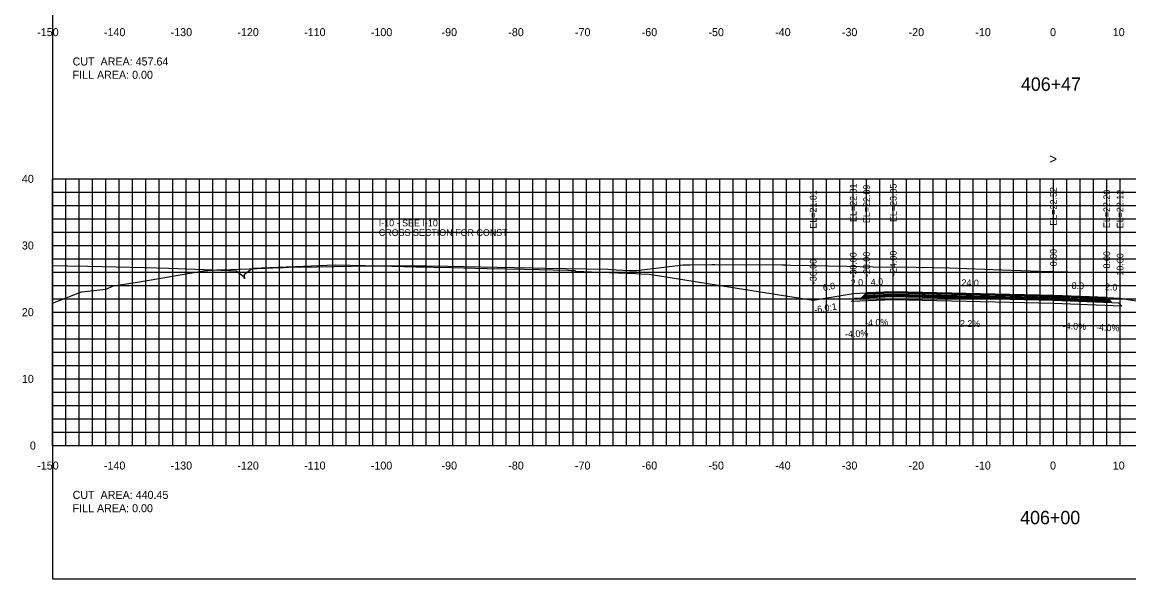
# Model space of a CAD drawing. Extents: x 1800976 to 1805104, y 250057 to 250580.
# Drawn here: x 1802816.4 to 1802982.3, y 250079.4 to 250162.9 of the extents above; entities that cross this region are included whole.
import ezdxf

# ---------------------------------------------------------------- set-up
doc = ezdxf.new("R2010")
doc.units = 0
for name, color, linetype in [('1', 7, 'Continuous'), ('10', 7, 'Continuous'), ('3', 7, 'Continuous'), ('31', 7, 'Continuous'), ('4', 7, 'Continuous'), ('60', 7, 'Continuous'), ('ANNO-TXT', 7, 'Continuous'), ('BASE', 7, 'Continuous'), ('CL-CNST', 7, 'Continuous'), ('Level 62', 7, 'Continuous'), ('LOWER BINDER', 7, 'Continuous'), ('M-ROADS', 7, 'Continuous'), ('UPPER BINDER', 7, 'Continuous'), ('WEARING', 7, 'Continuous')]:
    doc.layers.add(name, color=color, linetype=linetype)

msp = doc.modelspace()

# ---------------------------------------------------------------- linework, layer by layer
for p, q in [((1802941, 250122.24), (1802941, 250124.24)), ((1802943, 250122.32), (1802943, 250124.32)), ((1802947, 250122.48), (1802947, 250124.48)), ((1802971, 250121.95), (1802971, 250123.95)), ((1802979, 250121.63), (1802979, 250123.63)), ((1802935, 250121.24), (1802935, 250123.24)), ((1802981, 250121.55), (1802981, 250123.55))]:
    msp.add_line(p, q)
msp.add_lwpolyline([(1802821, 250079.43), (1803121, 250079.43), (1803121, 250269.43), (1802821, 250269.43)], close=True)
at = {"layer": '60'}
for p, q in [((1802820.94, 250139.43), (1802821, 250139.43)), ((1802821, 250099.43), (1802821, 250139.43)), ((1802820.94, 250129.43), (1802821, 250129.43)), ((1802820.94, 250119.43), (1802821, 250119.43)), ((1802820.94, 250109.43), (1802821, 250109.43)), ((1802820.94, 250099.43), (1802821, 250099.43)), ((1802821, 250099.43), (1803121, 250099.43)), ((1802821, 250099.37), (1802821, 250099.43)), ((1802831, 250099.37), (1802831, 250099.43)), ((1802841, 250099.37), (1802841, 250099.43)), ((1802851, 250099.37), (1802851, 250099.43)), ((1802861, 250099.37), (1802861, 250099.43)), ((1802871, 250099.37), (1802871, 250099.43)), ((1802881, 250099.37), (1802881, 250099.43)), ((1802891, 250099.37), (1802891, 250099.43)), ((1802901, 250099.37), (1802901, 250099.43)), ((1802911, 250099.37), (1802911, 250099.43)), ((1802921, 250099.37), (1802921, 250099.43)), ((1802931, 250099.37), (1802931, 250099.43)), ((1802941, 250099.37), (1802941, 250099.43)), ((1802951, 250099.37), (1802951, 250099.43)), ((1802961, 250099.37), (1802961, 250099.43)), ((1802971, 250099.37), (1802971, 250099.43)), ((1802981, 250099.37), (1802981, 250099.43))]:
    msp.add_line(p, q, dxfattribs=at)
at = {"layer": 'BASE'}
msp.add_lwpolyline([(1802941.25, 250121.53), (1802942.25, 250121.57), (1802947, 250121.76), (1802971, 250121.23), (1802979.75, 250120.88), (1802980.75, 250120.84), (1802981.27, 250120.32), (1802971, 250120.73), (1802947, 250121.26), (1802940.73, 250121.01)], close=True, dxfattribs=at)
at = {"layer": 'CL-CNST'}
for points in [[(1802821, 250126.43), (1802823.24, 250126.38), (1802826.27, 250126.31), (1802834.78, 250126.11), (1802838.4, 250126.03), (1802845.05, 250125.76), (1802848.51, 250125.61), (1802849.31, 250125.02), (1802849.77, 250124.69), (1802849.77, 250124.43), (1802849.77, 250124.86), (1802849.77, 250125.13), (1802850.57, 250125.71), (1802851.03, 250126.05), (1802858.59, 250126.34), (1802863.35, 250126.52), (1802870.03, 250126.37), (1802875.44, 250126.24), (1802880.78, 250126.12), (1802886.18, 250125.99), (1802891.75, 250125.86), (1802898.29, 250125.71), (1802898.72, 250125.69), (1802899.3, 250125.67), (1802899.33, 250125.64), (1802899.37, 250125.6), (1802903.07, 250125.44), (1802908.38, 250125.23), (1802909.16, 250125.2), (1802910.4, 250125.14), (1802926.77, 250122.53), (1802935, 250121.22)], [(1802935, 250121.24), (1802941, 250122.24), (1802943, 250122.32), (1802947, 250122.48), (1802971, 250121.95), (1802979, 250121.63), (1802981, 250121.55), (1803011, 250116.55), (1803015, 250116.55), (1803035.35, 250121.64)]]:
    msp.add_lwpolyline(points, dxfattribs=at)
at = {"layer": 'Level 62'}
for p, q in [((1802821, 250139.43), (1803121, 250139.43)), ((1802821, 250099.43), (1802821, 250139.43)), ((1802823, 250099.43), (1802823, 250139.43)), ((1802825, 250099.43), (1802825, 250139.43)), ((1802827, 250099.43), (1802827, 250139.43)), ((1802829, 250099.43), (1802829, 250139.43)), ((1802831, 250099.43), (1802831, 250139.43)), ((1802833, 250099.43), (1802833, 250139.43)), ((1802835, 250099.43), (1802835, 250139.43)), ((1802837, 250099.43), (1802837, 250139.43)), ((1802839, 250099.43), (1802839, 250139.43)), ((1802841, 250099.43), (1802841, 250139.43)), ((1802843, 250099.43), (1802843, 250139.43)), ((1802845, 250099.43), (1802845, 250139.43)), ((1802847, 250099.43), (1802847, 250139.43)), ((1802849, 250099.43), (1802849, 250139.43)), ((1802851, 250099.43), (1802851, 250139.43)), ((1802853, 250099.43), (1802853, 250139.43)), ((1802855, 250099.43), (1802855, 250139.43)), ((1802857, 250099.43), (1802857, 250139.43)), ((1802859, 250099.43), (1802859, 250139.43)), ((1802861, 250099.43), (1802861, 250139.43)), ((1802863, 250099.43), (1802863, 250139.43)), ((1802865, 250099.43), (1802865, 250139.43)), ((1802867, 250099.43), (1802867, 250139.43)), ((1802869, 250099.43), (1802869, 250139.43)), ((1802871, 250099.43), (1802871, 250139.43)), ((1802873, 250099.43), (1802873, 250139.43)), ((1802875, 250099.43), (1802875, 250139.43)), ((1802877, 250099.43), (1802877, 250139.43)), ((1802879, 250099.43), (1802879, 250139.43)), ((1802881, 250099.43), (1802881, 250139.43)), ((1802883, 250099.43), (1802883, 250139.43)), ((1802885, 250099.43), (1802885, 250139.43)), ((1802887, 250099.43), (1802887, 250139.43)), ((1802889, 250099.43), (1802889, 250139.43)), ((1802891, 250099.43), (1802891, 250139.43)), ((1802893, 250099.43), (1802893, 250139.43)), ((1802895, 250099.43), (1802895, 250139.43)), ((1802897, 250099.43), (1802897, 250139.43)), ((1802899, 250099.43), (1802899, 250139.43)), ((1802901, 250099.43), (1802901, 250139.43)), ((1802903, 250099.43), (1802903, 250139.43)), ((1802905, 250099.43), (1802905, 250139.43)), ((1802907, 250099.43), (1802907, 250139.43)), ((1802909, 250099.43), (1802909, 250139.43)), ((1802911, 250099.43), (1802911, 250139.43)), ((1802913, 250099.43), (1802913, 250139.43)), ((1802915, 250099.43), (1802915, 250139.43)), ((1802917, 250099.43), (1802917, 250139.43)), ((1802919, 250099.43), (1802919, 250139.43)), ((1802921, 250099.43), (1802921, 250139.43)), ((1802923, 250099.43), (1802923, 250139.43)), ((1802925, 250099.43), (1802925, 250139.43)), ((1802927, 250099.43), (1802927, 250139.43)), ((1802929, 250099.43), (1802929, 250139.43)), ((1802931, 250099.43), (1802931, 250139.43)), ((1802933, 250099.43), (1802933, 250139.43)), ((1802935, 250099.43), (1802935, 250139.43)), ((1802937, 250099.43), (1802937, 250139.43)), ((1802939, 250099.43), (1802939, 250139.43)), ((1802941, 250099.43), (1802941, 250139.43)), ((1802943, 250099.43), (1802943, 250139.43)), ((1802945, 250099.43), (1802945, 250139.43)), ((1802947, 250099.43), (1802947, 250139.43)), ((1802949, 250099.43), (1802949, 250139.43)), ((1802951, 250099.43), (1802951, 250139.43)), ((1802953, 250099.43), (1802953, 250139.43)), ((1802955, 250099.43), (1802955, 250139.43)), ((1802957, 250099.43), (1802957, 250139.43)), ((1802959, 250099.43), (1802959, 250139.43)), ((1802961, 250099.43), (1802961, 250139.43)), ((1802963, 250099.43), (1802963, 250139.43)), ((1802965, 250099.43), (1802965, 250139.43)), ((1802967, 250099.43), (1802967, 250139.43)), ((1802969, 250099.43), (1802969, 250139.43)), ((1802971, 250099.43), (1802971, 250139.43)), ((1802973, 250099.43), (1802973, 250139.43)), ((1802975, 250099.43), (1802975, 250139.43)), ((1802977, 250099.43), (1802977, 250139.43)), ((1802979, 250099.43), (1802979, 250139.43)), ((1802981, 250099.43), (1802981, 250139.43)), ((1802821, 250137.43), (1803121, 250137.43)), ((1802821, 250135.43), (1803121, 250135.43)), ((1802821, 250133.43), (1803121, 250133.43)), ((1802821, 250131.43), (1803121, 250131.43)), ((1802821, 250129.43), (1803121, 250129.43)), ((1802821, 250127.43), (1803121, 250127.43)), ((1802821, 250125.43), (1803121, 250125.43)), ((1802821, 250123.43), (1803121, 250123.43)), ((1802821, 250121.43), (1803121, 250121.43)), ((1802821, 250119.43), (1803121, 250119.43)), ((1802821, 250117.43), (1803121, 250117.43)), ((1802821, 250115.43), (1803121, 250115.43)), ((1802821, 250113.43), (1803121, 250113.43)), ((1802821, 250111.43), (1803121, 250111.43)), ((1802821, 250109.43), (1803121, 250109.43)), ((1802821, 250107.43), (1803121, 250107.43)), ((1802821, 250105.43), (1803121, 250105.43)), ((1802821, 250103.43), (1803121, 250103.43)), ((1802821, 250101.43), (1803121, 250101.43)), ((1802821, 250099.43), (1803121, 250099.43))]:
    msp.add_line(p, q, dxfattribs=at)
at = {"layer": 'LOWER BINDER'}
for points in [[(1802947, 250121.95), (1802971, 250121.42), (1802979.55, 250121.08), (1802979.75, 250120.88), (1802971, 250121.23), (1802947, 250121.76), (1802942.25, 250121.57), (1802942.45, 250121.77)], [(1802947, 250122.14), (1802971, 250121.61), (1802979.36, 250121.28), (1802979.55, 250121.08), (1802971, 250121.42), (1802947, 250121.95), (1802942.45, 250121.77), (1802942.65, 250121.97)]]:
    msp.add_lwpolyline(points, close=True, dxfattribs=at)
at = {"layer": 'M-ROADS'}
msp.add_lwpolyline([(1802821, 250120.8), (1802825.33, 250122.5), (1802828.53, 250122.82), (1802828.96, 250122.86), (1802830.15, 250123.38), (1802830.77, 250123.47), (1802833.74, 250123.95), (1802843.63, 250125.63), (1802845.61, 250125.76), (1802846.44, 250125.8), (1802850.45, 250125.95), (1802855.15, 250126.12), (1802855.56, 250126.13), (1802856.4, 250126.16), (1802860.59, 250126.23), (1802868.31, 250126.37), (1802877.09, 250126.36), (1802880.25, 250126.35), (1802887.64, 250126.2), (1802892.81, 250126.1), (1802894.82, 250126.05), (1802904.23, 250125.86), (1802904.79, 250125.83), (1802905.48, 250125.8), (1802907.48, 250125.7), (1802908.51, 250125.66), (1802915.53, 250126.51), (1802915.59, 250126.52), (1802915.62, 250126.52), (1802916.54, 250126.54), (1802919.83, 250126.58), (1802919.92, 250126.58), (1802920.28, 250126.58), (1802930.35, 250126.53), (1802931.06, 250126.51), (1802931.6, 250126.5), (1802940.03, 250126.34), (1802943.99, 250126.25), (1802950.42, 250126.16), (1802955.44, 250126.07), (1802963.26, 250125.77), (1802967.53, 250125.62), (1802968.45, 250125.6), (1802968.78, 250125.59), (1802973.17, 250125.48), (1802976.65, 250125.38), (1802979.29, 250125.41), (1802980.64, 250125.41), (1802982.5, 250125.44)], dxfattribs=at)
at = {"layer": 'UPPER BINDER'}
msp.add_lwpolyline([(1802979.36, 250121.28), (1802979.16, 250121.48), (1802971, 250121.8), (1802947, 250122.33), (1802942.85, 250122.16), (1802942.65, 250121.97), (1802947, 250122.14), (1802971, 250121.61)], close=True, dxfattribs=at)
at = {"layer": 'WEARING'}
msp.add_lwpolyline([(1802979.16, 250121.48), (1802979, 250121.63), (1802971, 250121.95), (1802947, 250122.48), (1802943, 250122.32), (1802942.85, 250122.16), (1802947, 250122.33), (1802971, 250121.8)], close=True, dxfattribs=at)

# ---------------------------------------------------------------- texts
msp.add_text('-6.0:1', height=1, rotation=9.4623).set_placement((1802935.24, 250119.27))
at = {"layer": '1'}
for s, p in [('406+47', (1802966.13, 250152.63)), ('406+00', (1802966.02, 250087.63))]:
    msp.add_text(s, height=2, dxfattribs=at).set_placement(p)
at = {"layer": '10'}
for s, p in [('-150', (1802818.7, 250160.83)), ('-140', (1802828.7, 250160.83)), ('-130', (1802838.7, 250160.83)), ('-120', (1802848.7, 250160.83)), ('-110', (1802858.7, 250160.83)), ('-100', (1802868.7, 250160.83)), ('-90', (1802879.3, 250160.83)), ('-80', (1802889.3, 250160.83)), ('-70', (1802899.3, 250160.83)), ('-60', (1802909.3, 250160.83)), ('-50', (1802919.3, 250160.83)), ('-40', (1802929.3, 250160.83)), ('-30', (1802939.3, 250160.83)), ('-20', (1802949.3, 250160.83)), ('-10', (1802959.3, 250160.83)), ('0', (1802970.5, 250160.83)), ('10', (1802979.9, 250160.83)), ('-150', (1802818.7, 250095.83)), ('-140', (1802828.7, 250095.83)), ('-130', (1802838.7, 250095.83)), ('-120', (1802848.7, 250095.83)), ('-110', (1802858.7, 250095.83)), ('-100', (1802868.7, 250095.83)), ('-90', (1802879.3, 250095.83)), ('-80', (1802889.3, 250095.83)), ('-70', (1802899.3, 250095.83)), ('-60', (1802909.3, 250095.83)), ('-50', (1802919.3, 250095.83)), ('-40', (1802929.3, 250095.83)), ('-30', (1802939.3, 250095.83)), ('-20', (1802949.3, 250095.83)), ('-10', (1802959.3, 250095.83)), ('0', (1802970.5, 250095.83)), ('10', (1802979.9, 250095.83))]:
    msp.add_text(s, height=1.2, dxfattribs=at).set_placement(p)
at = {"layer": '3'}
for s, p in [('EL=22.81', (1802941.5, 250132.96)), ('EL=23.05', (1802947.5, 250132.95)), ('EL=21.81', (1802935.5, 250131.96)), ('EL=22.89', (1802943.5, 250132.79)), ('EL=22.52', (1802971.5, 250132.42)), ('EL=22.20', (1802979.5, 250132.03)), ('EL=22.12', (1802981.5, 250132.02)), ('-24.00', (1802947.5, 250124.86)), ('0.00', (1802971.5, 250126.31)), ('-36.00', (1802935.5, 250123.62)), ('-30.00', (1802941.5, 250124.62)), ('-28.00', (1802943.5, 250124.7)), ('8.00', (1802979.5, 250125.99)), ('10.00', (1802981.5, 250124.92))]:
    msp.add_text(s, height=1, rotation=90, dxfattribs=at).set_placement(p)
for s, p in [('I-10 - SEE I-10 ', (1802869.89, 250132.31)), ('CROSS SECTION FOR CONST ', (1802869.89, 250130.87))]:
    msp.add_text(s, height=1, dxfattribs=at).set_placement(p)
at = {"layer": '31'}
for s, p in [('40', (1802816.4, 250138.83)), ('30', (1802816.4, 250128.83)), ('20', (1802816.4, 250118.83)), ('10', (1802816.4, 250108.83)), ('0', (1802817.6, 250098.83))]:
    msp.add_text(s, height=1.2, dxfattribs=at).set_placement(p)
at = {"layer": '4'}
for s, rotation, p in [('6.0', 9.4623, (1802936.52, 250122.61)), ('2.0', 2.2906, (1802940.64, 250123.33)), ('4.0', 2.2906, (1802943.64, 250123.45)), ('24.0', 358.7397, (1802957.21, 250123.36)), ('8.0', 357.7094, (1802973.72, 250122.94)), ('2.0', 357.7094, (1802978.72, 250122.74)), ('-4.0%', 2.2906, (1802942.79, 250117.31)), ('2.2%', 358.7397, (1802956.98, 250117.26)), ('-4.0%', 357.7094, (1802972.39, 250116.89)), ('-4.0%', 357.7094, (1802977.39, 250116.69)), ('-4.0%', 2.2906, (1802939.79, 250115.64))]:
    msp.add_text(s, height=1, rotation=rotation, dxfattribs=at).set_placement(p)
at = {"layer": '60'}
for s, height, p in [('>', 1.5, (1802970.39, 250141.68)), ('-', 0.0001, (1802821, 250099.43))]:
    msp.add_text(s, height=height, dxfattribs=at).set_placement(p)
at = {"layer": 'ANNO-TXT'}
for s, p in [('CUT  AREA: 457.64', (1802824, 250156.43)), ('FILL AREA: 0.00', (1802824, 250154.43)), ('CUT  AREA: 440.45', (1802824, 250091.43)), ('FILL AREA: 0.00', (1802824, 250089.43))]:
    msp.add_text(s, height=1.2, dxfattribs=at).set_placement(p)

doc.saveas('drawing.dxf')
